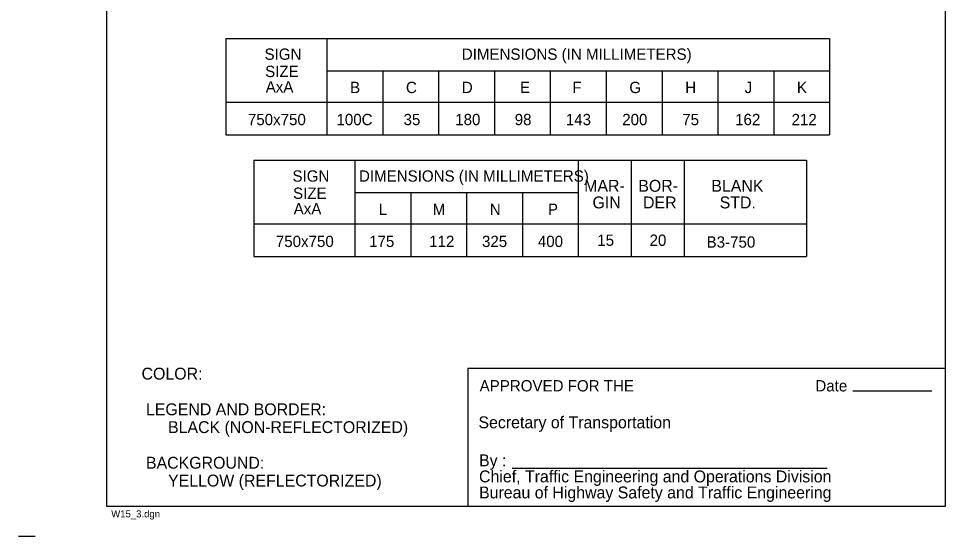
# Model space of a CAD drawing. Extents: x -0.018 to 0.195, y -0.006 to 0.263.
# Drawn here: x -0.0185 to 0.1765, y -0.0064 to 0.1026 of the extents above; entities that cross this region are included whole.
import ezdxf

# ---------------------------------------------------------------- set-up
doc = ezdxf.new("R2010")
doc.units = 0
doc.layers.add('1', color=7, linetype='Continuous')
doc.layers.add('3', color=7, linetype='Continuous')

msp = doc.modelspace()

# ---------------------------------------------------------------- linework, layer by layer
at = {"layer": '1'}
for p, q in [((0, 0.2565), (0, 0)), ((0.1765, 0), (0.1765, 0.2565)), ((0.076, 0.029), (0.1765, 0.029)), ((0.076, 0.029), (0.076, 0)), ((0.157, 0.02425), (0.17363, 0.02425)), ((0.08538, 0.008), (0.15163, 0.008)), ((0, 0), (0.1765, 0)), ((-0.015, -0.00638), (-0.0185, -0.00638))]:
    msp.add_line(p, q, dxfattribs=at)
at = {"layer": '3'}
for p, q in [((0.02513, 0.09838), (0.15213, 0.09838)), ((0.02513, 0.09838), (0.02513, 0.07812)), ((0.04637, 0.09838), (0.04637, 0.07812)), ((0.15213, 0.09838), (0.15213, 0.07812)), ((0.15213, 0.0915), (0.04637, 0.0915)), ((0.05813, 0.0915), (0.05813, 0.07812)), ((0.06988, 0.0915), (0.06988, 0.07812)), ((0.08163, 0.0915), (0.08163, 0.07812)), ((0.09337, 0.0915), (0.09337, 0.07812)), ((0.10512, 0.0915), (0.10512, 0.07812)), ((0.11688, 0.0915), (0.11688, 0.07812)), ((0.12862, 0.0915), (0.12862, 0.07812)), ((0.14037, 0.0915), (0.14037, 0.07812)), ((0.02513, 0.085), (0.15213, 0.085)), ((0.02513, 0.07812), (0.15213, 0.07812)), ((0.031, 0.07275), (0.14725, 0.07275)), ((0.031, 0.07275), (0.031, 0.0525)), ((0.05225, 0.07275), (0.05225, 0.0525)), ((0.09925, 0.07275), (0.09925, 0.0525)), ((0.11038, 0.07275), (0.11038, 0.0525)), ((0.1215, 0.07275), (0.1215, 0.0525)), ((0.14725, 0.07275), (0.14725, 0.0525)), ((0.09925, 0.06588), (0.05225, 0.06588)), ((0.064, 0.06588), (0.064, 0.0525)), ((0.07575, 0.06588), (0.07575, 0.0525)), ((0.0875, 0.06588), (0.0875, 0.0525)), ((0.031, 0.05938), (0.14725, 0.05938)), ((0.031, 0.0525), (0.14725, 0.0525))]:
    msp.add_line(p, q, dxfattribs=at)

# ---------------------------------------------------------------- texts
at = {"layer": '1'}
for s, height, p in [('COLOR:', 0.0025, (0.00738, 0.02662)), ('APPROVED FOR THE', 0.0023752, (0.0785, 0.02413)), ('Date ', 0.002375, (0.14913, 0.02413)), (' LEGEND AND BORDER:', 0.0024998, (0.00738, 0.01912)), ('      BLACK (NON-REFLECTORIZED)', 0.0024998, (0.00738, 0.01537)), ('Secretary of Transportation', 0.0024998, (0.07825, 0.01638)), (' BACKGROUND:', 0.0024998, (0.00738, 0.00788)), ('By :', 0.0025, (0.07838, 0.00838)), ('      YELLOW (REFLECTORIZED)', 0.0024998, (0.00738, 0.00413)), ('Chief, Traffic Engineering and Operations Division', 0.0024998, (0.07838, 0.005)), ('Bureau of Highway Safety and Traffic Engineering', 0.0024998, (0.07838, 0.00163)), ('W15_3.dgn', 0.0015, (0.001, -0.00237))]:
    msp.add_text(s, height=height, dxfattribs=at).set_placement(p)
at = {"layer": '3'}
for s, height, p in [('SIGN', 0.002375, (0.03325, 0.09388)), ('DIMENSIONS (IN MILLIMETERS)', 0.0023752, (0.07475, 0.09388)), ('SIZE', 0.002375, (0.03338, 0.09025)), ('AxA', 0.002375, (0.0335, 0.087)), ('B', 0.00238, (0.05125, 0.08688)), ('C', 0.00238, (0.063, 0.08688)), ('D', 0.00238, (0.07475, 0.08688)), ('E', 0.00238, (0.087, 0.08688)), ('F', 0.00238, (0.098, 0.08688)), ('G', 0.00238, (0.11, 0.08688)), ('H', 0.00238, (0.12175, 0.08688)), ('J', 0.00238, (0.13425, 0.08688)), ('K', 0.00238, (0.14525, 0.08688)), ('750x750', 0.002375, (0.02975, 0.08013)), ('100C', 0.002375, (0.04838, 0.08013)), ('35', 0.002375, (0.0625, 0.08013)), ('180', 0.002375, (0.07337, 0.08013)), ('98', 0.002375, (0.08588, 0.08013)), ('143', 0.002375, (0.09663, 0.08013)), ('200', 0.002375, (0.1085, 0.08013)), ('75', 0.002375, (0.12112, 0.08013)), ('162', 0.002375, (0.13225, 0.08013)), ('212', 0.002375, (0.14413, 0.08013)), ('SIGN', 0.002375, (0.03913, 0.06825)), ('DIMENSIONS (IN MILLIMETERS)', 0.0023752, (0.05312, 0.06825)), ('MAR-', 0.0025, (0.1005, 0.06613)), ('BOR-', 0.0025, (0.11188, 0.06613)), ('BLANK', 0.0025, (0.12725, 0.06613)), ('SIZE', 0.002375, (0.03925, 0.06463)), ('GIN', 0.0025, (0.10225, 0.06263)), ('DER', 0.0025, (0.11288, 0.06263)), ('STD.', 0.0025, (0.129, 0.06263)), ('AxA', 0.002375, (0.03938, 0.06137)), ('L', 0.00238, (0.05725, 0.06125)), ('M', 0.00238, (0.06863, 0.06125)), ('N', 0.00238, (0.08063, 0.06125)), ('P', 0.00238, (0.09287, 0.06125)), ('750x750', 0.002375, (0.03563, 0.0545)), ('175', 0.002375, (0.05525, 0.0545)), ('112', 0.002375, (0.06788, 0.0545)), ('325', 0.002375, (0.079, 0.0545)), ('400', 0.002375, (0.09075, 0.0545)), ('15', 0.002375, (0.10325, 0.05475)), ('20', 0.002375, (0.11425, 0.05475)), ('B3-750', 0.002375, (0.12625, 0.05437))]:
    msp.add_text(s, height=height, dxfattribs=at).set_placement(p)

doc.saveas('drawing.dxf')
